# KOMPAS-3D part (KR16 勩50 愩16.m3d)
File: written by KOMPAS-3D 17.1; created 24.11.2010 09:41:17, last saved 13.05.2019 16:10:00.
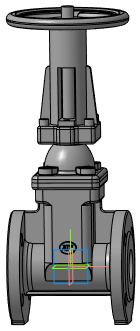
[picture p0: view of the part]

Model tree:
1. Плоскость XY
2. Плоскость ZX
3. Плоскость ZY
4. Ось X
5. Ось Y
6. Ось Z
7. Начало координат
8. Операция без истории:2
9. Элемент выдавливания:1
     Расстояние 2 = 1
10. Элемент выдавливания:2
     Расстояние 2 = 1
11. Элемент выдавливания:3
     Расстояние 2 = 1
12. Элемент выдавливания:4
     Расстояние 2 = 1
13. Элемент выдавливания:5
     Расстояние 2 = 1
14. Элемент выдавливания:6
     Расстояние 2 = 1
15. Элемент выдавливания:7
     Расстояние 2 = 1
16. Элемент выдавливания:8
     Расстояние 2 = 1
